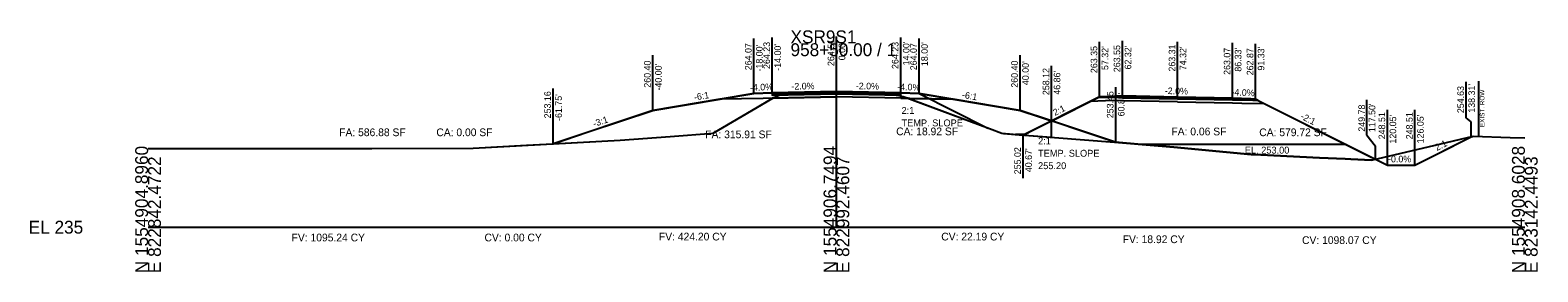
# Model space of a CAD drawing. Extents: x -26 to 823017, y -16 to 1558356.
# Drawn here: x -25.7 to 302.8, y 6490.3 to 6542.8 of the extents above; entities that cross this region are included whole.
import ezdxf

# ---------------------------------------------------------------- set-up
doc = ezdxf.new("R2010")
doc.units = 0
for name, color, linetype in [('ASPHALT_19MM1', 7, 'Continuous'), ('ASPHALT_9_5MM1', 7, 'Continuous'), ('CONST_DCH', 7, 'Continuous'), ('CONST_LV3', 7, 'Continuous'), ('Default', 7, 'Continuous'), ('Draft_XS_Grid', 7, 'Continuous'), ('DTM_CORRIDOR', 7, 'Continuous'), ('DTM_P_FINISHED_GRADE2', 7, 'Continuous'), ('DTM_TEMP_DROP', 7, 'Continuous'), ('DTM_X_GROUND', 7, 'Continuous'), ('PROFILES_DCH_2', 7, 'Continuous'), ('SLOPE_STAKES_FILL', 7, 'Continuous'), ('XS_CELL', 7, 'Continuous'), ('XS_M_SHAPES_EARTHWORK', 7, 'Continuous'), ('XS_P_ASPHALT', 7, 'Continuous'), ('XS_P_DR_GRAVEL', 7, 'Continuous'), ('XS_P_GROUND', 7, 'Continuous'), ('XS_P_NULL_POINT', 7, 'Continuous'), ('XS_P_SHOULDER', 7, 'Continuous'), ('XS_P_SUBGRADE_GRANULAR', 7, 'Continuous'), ('XS_P_SUBGRADE_MILLING', 7, 'Continuous'), ('XS_P_SUBGRADE_UNDERCUT', 7, 'Continuous'), ('XS_P_TX_CLEARZONE', 7, 'Continuous'), ('XS_P_TX_FS_BS', 7, 'Continuous'), ('XS_SHEET_EW_TX_AREA', 7, 'Continuous'), ('XS_SHEET_EW_TX_VOLUME', 7, 'Continuous'), ('XS_X_ROW', 7, 'Continuous')]:
    doc.layers.add(name, color=color, linetype=linetype)

msp = doc.modelspace()

# ---------------------------------------------------------------- linework, layer by layer
at = {"layer": 'ASPHALT_19MM1'}
for points in [[(136, 6528.94), (136, 6528.73), (150, 6529.01), (150, 6529.01), (150, 6529.01), (164, 6528.73), (164, 6528.94), (164, 6528.94), (150, 6529.22), (150, 6529.22), (150, 6529.22), (136, 6528.94), (136, 6528.94)], [(212.32, 6528.17), (224.32, 6527.93), (236.33, 6527.69), (236.33, 6527.9), (224.32, 6528.14), (212.32, 6528.38), (212.32, 6528.17)]]:
    msp.add_lwpolyline(points, dxfattribs=at)
at = {"layer": 'ASPHALT_9_5MM1'}
msp.add_lwpolyline([(136, 6529.23), (136, 6529.11), (150, 6529.39), (150, 6529.39), (150, 6529.39), (164, 6529.11), (164, 6529.23), (164, 6529.23), (150, 6529.51), (150, 6529.51), (150, 6529.51), (136, 6529.23), (136, 6529.23)], dxfattribs=at)
at = {"layer": 'CONST_DCH'}
msp.add_lwpolyline([(212.32, 6528.38), (224.32, 6528.14), (236.33, 6527.9), (236.33, 6528.07), (224.32, 6528.31), (212.32, 6528.55), (212.32, 6528.38)], dxfattribs=at)
at = {"layer": 'CONST_LV3'}
for points in [[(150, 6529.51), (164, 6529.23)], [(168, 6529.07), (164, 6529.23), (164, 6529.23)], [(190.67, 6520.02), (193.26, 6521.32), (207.32, 6528.35), (208.16, 6528.38), (212.32, 6528.55)], [(196.86, 6523.12), (196.86, 6523.12), (196.9, 6523.14), (196.91, 6523.14), (207.32, 6528.35), (208.16, 6528.38), (212.32, 6528.55), (214.42, 6528.5), (224.32, 6528.31), (233.92, 6528.11), (236.33, 6528.07), (240.29, 6527.91), (241.33, 6527.87), (263.21, 6516.93), (270.05, 6513.51), (274.56, 6513.51), (276.05, 6513.51), (278.82, 6514.89), (280.54, 6515.75), (280.81, 6515.89), (288.31, 6519.63), (288.58, 6519.71), (288.73, 6519.82), (296.83, 6519.53), (300, 6519.42)], [(110, 6525.4), (124.59, 6527.84), (124.59, 6527.84)], [(190, 6525.4), (175.41, 6527.84), (175.41, 6527.84)], [(241.33, 6527.87), (267.5, 6514.78)], [(0, 6517.13), (7.94, 6517.14), (20.48, 6517.15), (48.76, 6517.12), (70.81, 6517.2), (82.43, 6517.84), (88.16, 6518.15), (88.25, 6518.16)]]:
    msp.add_lwpolyline(points, dxfattribs=at)
at = {"layer": 'Default'}
msp.add_lwpolyline([(136, 6529.11), (136, 6528.94), (150, 6529.22), (150, 6529.22), (150, 6529.22), (164, 6528.94), (164, 6529.11), (164, 6529.11), (150, 6529.39), (150, 6529.39), (150, 6529.39), (136, 6529.11), (136, 6529.11)], dxfattribs=at)
at = {"layer": 'DTM_P_FINISHED_GRADE2'}
msp.add_lwpolyline([(88.25, 6518.16), (88.26, 6518.16), (88.27, 6518.16), (95.92, 6520.71), (110, 6525.4), (132, 6529.07), (132, 6529.07), (132, 6529.07), (136, 6529.23), (138, 6529.27), (150, 6529.51), (162, 6529.27), (162, 6529.27), (164, 6529.23), (168, 6529.07), (182.26, 6526.69), (190, 6525.4), (190, 6525.4), (190, 6525.4), (194.44, 6523.92), (196.86, 6523.12), (196.86, 6523.12), (196.86, 6523.12)], dxfattribs=at)
at = {"layer": 'DTM_X_GROUND'}
for points in [[(0, 6517.13), (7.94, 6517.14), (20.48, 6517.15), (48.76, 6517.12), (70.81, 6517.2), (82.43, 6517.84), (88.16, 6518.15), (88.25, 6518.16), (88.26, 6518.16), (88.27, 6518.16), (95.92, 6520.71), (110, 6525.4), (110, 6525.4), (132, 6529.07), (132, 6529.07), (136, 6529.23), (138, 6529.27), (138, 6529.27), (138, 6529.27), (138, 6529.27), (150, 6529.51), (162, 6529.27), (162, 6529.27), (162, 6529.27), (162, 6529.27), (164, 6529.23), (164, 6529.23), (168, 6529.07), (182.26, 6526.69), (190, 6525.4), (190, 6525.4), (190, 6525.4), (194.44, 6523.92), (196.86, 6523.12), (196.86, 6523.12), (196.86, 6523.12), (196.86, 6523.12), (196.9, 6523.14), (196.91, 6523.14), (207.32, 6528.35), (208.16, 6528.38), (212.32, 6528.55), (214.42, 6528.5), (224.32, 6528.31), (233.92, 6528.11), (236.33, 6528.07), (240.29, 6527.91), (241.33, 6527.87), (263.21, 6516.93), (270.05, 6513.51), (274.56, 6513.51), (276.05, 6513.51), (278.82, 6514.89), (280.54, 6515.75), (280.81, 6515.89), (288.31, 6519.63), (288.58, 6519.71), (288.73, 6519.82), (296.83, 6519.53), (300, 6519.42)], [(0, 6517.13), (7.94, 6517.14), (20.48, 6517.15), (48.76, 6517.12), (70.81, 6517.2), (102.89, 6518.96), (113.79, 6519.75), (123.12, 6520.43), (131.54, 6525.39), (136.33, 6528.18), (136.88, 6528.4), (137.65, 6528.76), (144.81, 6528.93), (150.27, 6529.06), (161.16, 6528.79), (163, 6528.74), (163.22, 6528.7), (164.55, 6528.42), (183.35, 6521.44), (186.07, 6520.42), (190.97, 6520.05), (210.62, 6518.47), (220.14, 6517.71), (221.01, 6517.61), (223.53, 6517.38), (234.99, 6516.29), (240.4, 6515.82), (242.48, 6515.72), (255.23, 6515.08), (260.84, 6514.86), (262.08, 6514.82), (266.61, 6514.57), (281.72, 6518.14), (288.73, 6519.82), (296.83, 6519.53), (300, 6519.42)], [(0, 6517.13), (7.94, 6517.14), (20.48, 6517.15), (48.76, 6517.12), (70.81, 6517.2), (102.89, 6518.96), (113.79, 6519.75), (123.12, 6520.43), (131.54, 6525.39), (136.33, 6528.18), (136.88, 6528.4), (137.65, 6528.76), (144.81, 6528.93), (150.27, 6529.06), (161.16, 6528.79), (163, 6528.74), (163.22, 6528.7), (164.55, 6528.42), (183.35, 6521.44), (186.07, 6520.42), (186.4, 6520.39), (190.67, 6520.02), (190.72, 6520.05), (191.33, 6520.35), (192.5, 6520.94), (193.26, 6521.32), (207.32, 6528.35), (208.16, 6528.38), (212.32, 6528.55), (214.42, 6528.5), (224.32, 6528.31), (233.92, 6528.11), (236.33, 6528.07), (240.29, 6527.91), (241.33, 6527.87), (263.21, 6516.93), (270.05, 6513.51), (274.56, 6513.51), (276.05, 6513.51), (278.82, 6514.89), (280.54, 6515.75), (280.81, 6515.89), (288.31, 6519.63), (288.58, 6519.71), (288.73, 6519.82), (296.83, 6519.53), (300, 6519.42)]]:
    msp.add_lwpolyline(points, dxfattribs=at)
at = {"layer": 'XS_CELL'}
for p, q in [((150, 6500), (150, 6540)), ((0, 6500), (150, 6500)), ((150, 6500), (300, 6500))]:
    msp.add_line(p, q, dxfattribs=at)
at = {"layer": 'XS_M_SHAPES_EARTHWORK'}
for points in [[(88.25, 6518.16), (102.89, 6518.96), (113.79, 6519.75), (123.12, 6520.43), (131.54, 6525.39), (136.13, 6528.07), (136, 6528.06), (134, 6528.02), (124.59, 6527.84), (110, 6525.4)], [(136.13, 6528.07), (136.33, 6528.18), (136.88, 6528.4), (137.65, 6528.76), (144.81, 6528.93), (150.27, 6529.06), (161.16, 6528.79), (163, 6528.74), (163.22, 6528.7), (164.55, 6528.42), (165.61, 6528.03), (164, 6528.06), (150, 6528.34)], [(165.61, 6528.03), (183.35, 6521.44), (186.07, 6520.42), (190.97, 6520.05), (196.86, 6519.58), (196.86, 6523.12), (190, 6525.4), (175.41, 6527.84), (166, 6528.02)]]:
    msp.add_lwpolyline(points, close=True, dxfattribs=at)
at = {"layer": 'XS_P_DR_GRAVEL'}
for points in [[(208.16, 6528.38), (207.32, 6528.35), (207.2, 6528.29), (207.18, 6528.27), (211.43, 6528.19), (212.32, 6528.17), (212.32, 6528.24), (212.32, 6528.55), (208.16, 6528.38)], [(240.29, 6527.91), (236.33, 6528.07), (236.33, 6527.77), (236.33, 6527.69), (240.74, 6527.6), (241.9, 6527.58), (241.78, 6527.64), (241.33, 6527.87), (240.29, 6527.91)]]:
    msp.add_lwpolyline(points, dxfattribs=at)
at = {"layer": 'XS_P_GROUND'}
for p, q in [((168, 6529.07), (183.02, 6521.56)), ((189.01, 6520.2), (191.02, 6520.2))]:
    msp.add_line(p, q, dxfattribs=at)
for points in [[(132, 6529.07), (110, 6525.4), (88.25, 6518.16)], [(196.86, 6523.12), (196.86, 6523.12), (190, 6525.4), (168, 6529.07), (168, 6529.07)], [(210.85, 6518.45), (210.85, 6518.45), (190, 6525.4), (168, 6529.07), (168, 6529.07)], [(207.32, 6528.35), (190.67, 6520.02)], [(241.33, 6527.87), (270.05, 6513.51), (276.05, 6513.51), (288.31, 6519.63)], [(267.5, 6514.78), (267.5, 6514.78), (267.5, 6514.78), (266.61, 6514.57), (266.61, 6514.57), (262.08, 6514.82), (262.08, 6514.82), (262.08, 6514.82), (260.84, 6514.86), (255.23, 6515.08), (255.23, 6515.08), (255.23, 6515.08), (255.23, 6515.08), (242.48, 6515.72), (242.48, 6515.72), (240.4, 6515.82), (234.99, 6516.29), (234.99, 6516.29), (223.53, 6517.38), (221.01, 6517.61), (220.14, 6517.71), (220.14, 6517.71), (220.14, 6517.71), (210.85, 6518.45)], [(267.5, 6514.78), (267.5, 6514.78), (267.5, 6514.78), (266.61, 6514.57), (266.61, 6514.57), (262.08, 6514.82), (262.08, 6514.82), (262.08, 6514.82), (260.84, 6514.86), (255.23, 6515.08), (255.23, 6515.08), (255.23, 6515.08), (255.23, 6515.08), (242.48, 6515.72), (242.48, 6515.72), (240.4, 6515.82), (234.99, 6516.29), (234.99, 6516.29), (223.53, 6517.38), (221.01, 6517.61), (220.14, 6517.71), (220.14, 6517.71), (220.14, 6517.71), (210.85, 6518.45)]]:
    msp.add_lwpolyline(points, dxfattribs=at)
at = {"layer": 'XS_P_SHOULDER'}
for points in [[(136, 6529.23), (132, 6529.07)], [(164, 6529.23), (168, 6529.07)], [(207.32, 6528.35), (208.16, 6528.38), (212.32, 6528.55)], [(241.33, 6527.87), (240.29, 6527.91), (236.33, 6528.07)]]:
    msp.add_lwpolyline(points, dxfattribs=at)
at = {"layer": 'XS_P_SUBGRADE_GRANULAR'}
for points in [[(136, 6528.06), (134, 6528.02), (124.59, 6527.84)], [(136, 6528.06), (150, 6528.34), (150, 6528.34)], [(164, 6528.06), (150, 6528.34), (150, 6528.34)], [(164, 6528.06), (166, 6528.02), (175.41, 6527.84)], [(212.32, 6527.5), (210.32, 6527.54), (205.32, 6527.34)], [(224.32, 6527.26), (212.32, 6527.5)], [(224.32, 6527.26), (236.33, 6527.02)], [(236.33, 6527.02), (238.33, 6526.98), (243.29, 6526.89)]]:
    msp.add_lwpolyline(points, dxfattribs=at)
at = {"layer": 'XS_P_SUBGRADE_UNDERCUT'}
msp.add_lwpolyline([(216.48, 6518), (210.84, 6518.46), (196.86, 6523.12), (207.32, 6528.35), (212.32, 6528.55), (224.32, 6528.31), (236.33, 6528.07), (241.33, 6527.87), (261.06, 6518)], close=True, dxfattribs=at)
at = {"layer": 'XS_P_TX_CLEARZONE'}
for p, q in [((136, 6529.23), (136, 6541.23)), ((150, 6529.51), (150, 6541.51)), ((164, 6529.23), (164, 6541.23)), ((132, 6529.07), (132, 6541.07)), ((168, 6529.07), (168, 6541.07)), ((168, 6529.07), (168, 6541.07)), ((207.32, 6528.35), (207.32, 6540.35)), ((212.32, 6528.55), (212.32, 6540.55)), ((224.32, 6528.31), (224.32, 6540.31)), ((236.33, 6528.07), (236.33, 6540.07)), ((241.33, 6527.87), (241.33, 6539.87)), ((110, 6525.4), (110, 6537.4)), ((190, 6525.4), (190, 6537.4)), ((190, 6525.4), (190, 6537.4)), ((196.86, 6523.12), (196.86, 6535.12)), ((287.21, 6523.82), (287.21, 6531.63)), ((88.25, 6518.16), (88.25, 6530.16)), ((210.85, 6518.45), (210.85, 6530.45)), ((265.54, 6519.99), (265.54, 6527.7)), ((270.05, 6513.51), (270.05, 6525.51)), ((276.05, 6513.51), (276.05, 6525.51)), ((288.31, 6522.94), (287.21, 6523.82)), ((288.31, 6519.63), (288.31, 6522.94)), ((190.67, 6510.69), (190.67, 6520.02)), ((265.54, 6519.99), (267.5, 6517.6)), ((267.5, 6514.78), (267.5, 6517.6))]:
    msp.add_line(p, q, dxfattribs=at)
at = {"layer": 'XS_X_ROW'}
msp.add_line((290, 6519.78), (290, 6531.78), dxfattribs=at)

# ---------------------------------------------------------------- texts
at = {"layer": 'CONST_DCH'}
for p in [(190.59, 6519.9), (267.42, 6514.66), (269.97, 6513.39)]:
    msp.add_text('X', height=0.24, dxfattribs=at).set_placement(p)
at = {"layer": 'Draft_XS_Grid'}
msp.add_text('-', height=0.0001, dxfattribs=at).set_placement((0, 6500))
at = {"layer": 'DTM_CORRIDOR'}
for p in [(212.24, 6528.43), (224.25, 6528.19), (236.25, 6527.95)]:
    msp.add_text('X', height=0.24, dxfattribs=at).set_placement(p)
at = {"layer": 'DTM_TEMP_DROP'}
for p in [(135.92, 6529.11), (149.92, 6529.39), (163.92, 6529.11)]:
    msp.add_text('X', height=0.24, dxfattribs=at).set_placement(p)
at = {"layer": 'PROFILES_DCH_2'}
for p in [(167.92, 6528.95), (189.92, 6525.28), (210.78, 6518.33), (267.42, 6514.66)]:
    msp.add_text('X', height=0.24, dxfattribs=at).set_placement(p)
at = {"layer": 'SLOPE_STAKES_FILL'}
for p in [(196.78, 6523), (88.18, 6518.04)]:
    msp.add_text('X', height=0.24, dxfattribs=at).set_placement(p)
at = {"layer": 'XS_CELL'}
for s, p in [('XSR9S1', (140, 6540)), ('958+50.00 / 1', (140, 6537.2)), ('EL 235', (-26, 6498.6))]:
    msp.add_text(s, height=2.8, dxfattribs=at).set_placement(p)
for s, p in [('N 1554904.8960', (0, 6490)), ('E 822842.4722', (2.8, 6490)), ('N 1554906.7494', (150, 6490)), ('E 822992.4607', (152.8, 6490)), ('N 1554908.6028', (300, 6490)), ('E 823142.4493', (302.8, 6490))]:
    msp.add_text(s, height=2.8, rotation=90, dxfattribs=at).set_placement(p)
at = {"layer": 'XS_P_ASPHALT'}
for p in [(190.59, 6519.9), (288.23, 6519.51)]:
    msp.add_text('X', height=0.24, dxfattribs=at).set_placement(p)
at = {"layer": 'XS_P_GROUND'}
for s, p in [('2:1', (164.18, 6524.64)), ('TEMP. SLOPE', (164.18, 6521.94)), ('2:1', (193.94, 6518.03)), ('TEMP. SLOPE', (193.94, 6515.33)), ('255.20', (193.94, 6512.63))]:
    msp.add_text(s, height=1.5, dxfattribs=at).set_placement(p)
at = {"layer": 'XS_P_NULL_POINT'}
for p in [(196.78, 6523), (88.18, 6518.04), (275.97, 6513.39)]:
    msp.add_text('X', height=0.24, dxfattribs=at).set_placement(p)
at = {"layer": 'XS_P_SHOULDER'}
for p in [(207.24, 6528.23), (241.25, 6527.75), (109.92, 6525.28), (189.92, 6525.28)]:
    msp.add_text('X', height=0.24, dxfattribs=at).set_placement(p)
at = {"layer": 'XS_P_SUBGRADE_MILLING'}
for p in [(131.92, 6528.95), (167.92, 6528.95)]:
    msp.add_text('X', height=0.24, dxfattribs=at).set_placement(p)
at = {"layer": 'XS_P_SUBGRADE_UNDERCUT'}
msp.add_text('EL. 253.00', height=1.5, dxfattribs=at).set_placement((238.99, 6516.01))
at = {"layer": 'XS_P_TX_CLEARZONE'}
for s, p in [('264.07', (131.52, 6534.14)), ("-18.00'", (133.92, 6533.86)), ('264.23', (135.52, 6534.41)), ("-14.00'", (137.92, 6534.02)), ('264.51', (149.52, 6535.05)), ("0.00'", (151.92, 6536.3)), ('264.23', (163.52, 6534.41)), ("14.00'", (165.92, 6535.2)), ('264.07', (167.52, 6534.14)), ("18.00'", (169.92, 6535.04)), ('263.35', (206.84, 6533.52)), ("57.32'", (209.24, 6534.18)), ('263.55', (211.84, 6533.72)), ("62.32'", (214.24, 6534.31)), ('263.31', (223.84, 6533.85)), ("74.32'", (226.24, 6534.14)), ('263.07', (235.85, 6533.13)), ("86.33'", (238.25, 6533.83)), ('262.87', (240.85, 6533.04)), ("91.33'", (243.25, 6534.06)), ('260.40', (109.52, 6530.34)), ("-40.00'", (111.92, 6529.72)), ('260.40', (189.52, 6530.34)), ("40.00'", (191.92, 6530.9)), ('258.12', (196.38, 6528.73)), ("46.86'", (198.78, 6528.82)), ('253.16', (87.77, 6523.68)), ("-61.75'", (90.17, 6523.11)), ('253.45', (210.37, 6523.7)), ("60.85'", (212.77, 6524.11)), ('254.63', (286.73, 6524.81)), ("138.31'", (289.13, 6524.9)), ('249.78', (265.18, 6520.78)), ("117.50'", (267.44, 6520.67)), ('248.51', (269.57, 6519.12)), ('248.51', (275.57, 6519.12)), ("120.05'", (271.97, 6518.19)), ("126.05'", (277.97, 6518.23)), ('255.02', (190.19, 6511.51)), ("40.67'", (192.59, 6511.97))]:
    msp.add_text(s, height=1.44, rotation=90, dxfattribs=at).set_placement(p)
at = {"layer": 'XS_P_TX_FS_BS'}
for s, rotation, p in [('-4.0%', 2.2906, (131.18, 6529.64)), ('-2.0%', 1.1458, (140.2, 6529.91)), ('-2.0%', 358.8542, (154.22, 6530.03)), ('-4.0%', 357.7094, (163.23, 6529.86)), ('-6:1', 9.4642, (119.08, 6527.53)), ('-6:1', 350.5377, (177.28, 6528.13)), ('-2.0%', 358.8542, (221.54, 6528.96)), ('-4.0%', 357.7096, (236.06, 6528.68)), ('2:1', 26.5592, (197.63, 6524.17)), ('-3:1', 18.4332, (97.22, 6521.78)), ('-2:1', 333.4403, (250.99, 6523.65)), ('2:1', 26.5523, (280.82, 6516.56)), ('-0.0%', 359.9954, (270.2, 6514.11))]:
    msp.add_text(s, height=1.44, rotation=rotation, dxfattribs=at).set_placement(p)
at = {"layer": 'XS_SHEET_EW_TX_AREA'}
for s, p in [('FA: 586.88 SF', (41.65, 6519.8)), ('CA: 0.00 SF', (62.82, 6519.8)), ('CA: 18.92 SF', (163.02, 6520)), ('FA: 0.06 SF', (222.99, 6519.98)), ('CA: 579.72 SF', (242.13, 6519.8)), ('FA: 315.91 SF', (121.42, 6519.35))]:
    msp.add_text(s, height=1.68, dxfattribs=at).set_placement(p)
at = {"layer": 'XS_SHEET_EW_TX_VOLUME'}
for s, p in [('FV: 1095.24 CY', (31.28, 6496.92)), ('CV: 0.00 CY', (73.31, 6496.92)), ('FV: 424.20 CY', (111.32, 6497.12)), ('CV: 22.19 CY', (172.84, 6497.12)), ('FV: 18.92 CY', (212.38, 6496.54)), ('CV: 1098.07 CY', (251.46, 6496.35))]:
    msp.add_text(s, height=1.68, dxfattribs=at).set_placement(p)
at = {"layer": 'XS_X_ROW'}
msp.add_text('EXIST. ROW', height=1, rotation=90, dxfattribs=at).set_placement((291.2, 6521.78))

doc.saveas('drawing.dxf')
